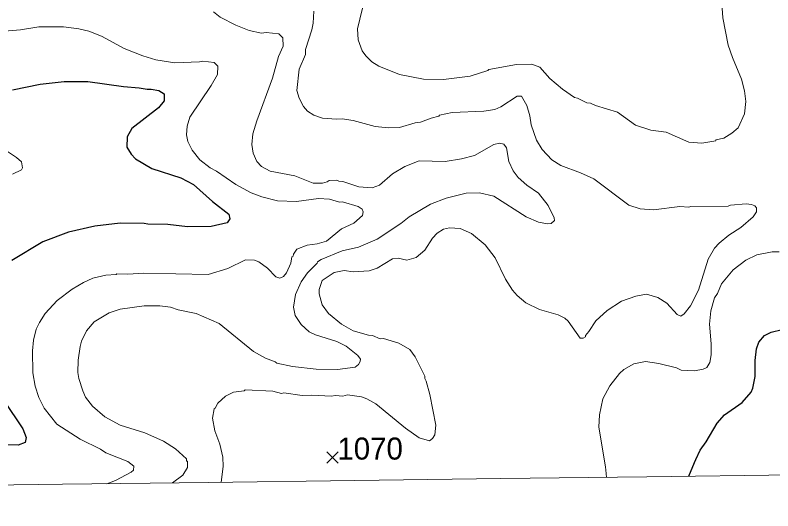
# Model space of a CAD drawing. Extents: x 265.7 to 292.1, y 7676.2 to 7704.2.
# Drawn here: x 287.156 to 289.907, y 7676.365 to 7678.165 of the extents above; entities that cross this region are included whole.
import ezdxf
from ezdxf.enums import TextEntityAlignment as Align

# ---------------------------------------------------------------- set-up
doc = ezdxf.new("R2010")
doc.units = 0
doc.header["$LTSCALE"] = 0.032
for name, color, linetype, lineweight in [('1', 7, 'Continuous', 25), ('2', 7, 'Continuous', 13), ('21', 7, 'Continuous', 25), ('63', 7, 'Continuous', 25)]:
    doc.layers.add(name, color=color, linetype=linetype, lineweight=lineweight)
doc.layers.add('61', color=7, linetype='Continuous')

msp = doc.modelspace()

# ---------------------------------------------------------------- linework, layer by layer
at = {"layer": '1'}
for points in [[(287.1465, 7677.8935), (287.2471, 7677.9142), (287.3333, 7677.9246), (287.4194, 7677.9238), (287.5487, 7677.9055), (287.6062, 7677.9015), (287.6349, 7677.8959), (287.6493, 7677.8967), (287.678, 7677.8911), (287.6971, 7677.8791), (287.6963, 7677.8536), (287.6764, 7677.8281), (287.579, 7677.7538), (287.5631, 7677.7227), (287.5615, 7677.686), (287.5766, 7677.6605), (287.5926, 7677.6429), (287.6516, 7677.6078), (287.7578, 7677.5743), (287.8033, 7677.5496), (287.8727, 7677.4881), (287.9317, 7677.4426), (287.9349, 7677.4259), (287.9253, 7677.4107), (287.8679, 7677.398), (287.7817, 7677.3964), (287.7099, 7677.4043), (287.6381, 7677.4059), (287.6237, 7677.4091), (287.5375, 7677.4099), (287.445, 7677.3987), (287.3492, 7677.3772), (287.2567, 7677.3421), (287.1433, 7677.2743)], [(289.6017, 7676.4904), (289.6218, 7676.5401), (289.6273, 7676.5511), (289.6425, 7676.5848), (289.6649, 7676.616), (289.704, 7676.6838), (289.7311, 7676.7141), (289.795, 7676.7588), (289.8277, 7676.7955), (289.8341, 7676.8099), (289.8428, 7676.853), (289.8428, 7676.9104), (289.8468, 7676.9535), (289.8556, 7676.9774), (289.8764, 7677.0014), (289.9003, 7677.0133), (289.941, 7677.0237)], [(287.1146, 7676.7652), (287.184, 7676.663), (287.196, 7676.6311), (287.1928, 7676.6128), (287.1673, 7676.604), (287.1242, 7676.6048)]]:
    msp.add_lwpolyline(points, dxfattribs=at)
at = {"layer": '2'}
msp.add_line((287.4887, 7676.4636), (287.52, 7676.4752), dxfattribs=at)
for points in [[(289.7208, 7678.227), (289.7255, 7678.1552), (289.7447, 7678.0563), (289.7599, 7678.0108), (289.7926, 7677.9326), (289.8037, 7677.8903), (289.8085, 7677.852), (289.8037, 7677.8073), (289.7806, 7677.7555), (289.7575, 7677.7363), (289.7287, 7677.7187), (289.7, 7677.7124), (289.6992, 7677.7092), (289.6489, 7677.7004), (289.6011, 7677.7044), (289.5197, 7677.7403), (289.4638, 7677.7475), (289.408, 7677.7658), (289.3425, 7677.8129), (289.2627, 7677.8368), (289.2444, 7677.8456), (289.2308, 7677.8472), (289.1973, 7677.864), (289.1869, 7677.8656), (289.143, 7677.8967), (289.0976, 7677.935), (289.0608, 7677.9757), (289.0313, 7677.9869), (288.9755, 7677.9861), (288.8757, 7677.9677), (288.8717, 7677.9637), (288.8079, 7677.9438), (288.7105, 7677.9318), (288.6387, 7677.9326), (288.551, 7677.9493), (288.4759, 7677.9797), (288.4512, 7677.9956), (288.4289, 7678.0172), (288.4153, 7678.0355), (288.4009, 7678.0754), (288.3993, 7678.1153), (288.4249, 7678.227)], [(287.8759, 7678.1768), (287.8998, 7678.1584), (287.9573, 7678.1289), (288.0051, 7678.1097), (288.0498, 7678.1002), (288.0674, 7678.1026), (288.1129, 7678.0978), (288.128, 7678.0826), (288.1288, 7678.0523), (288.1121, 7678.0148), (288.0897, 7677.9366), (288.0331, 7677.7818), (288.0187, 7677.7339), (288.0155, 7677.6956), (288.0203, 7677.6637), (288.0339, 7677.6334), (288.0498, 7677.6158), (288.0817, 7677.599), (288.1711, 7677.5815), (288.2381, 7677.5544), (288.2717, 7677.5552), (288.2892, 7677.5599), (288.2956, 7677.5647), (288.3227, 7677.5663), (288.3315, 7677.5623), (288.3459, 7677.5615), (288.4041, 7677.5416), (288.452, 7677.5384), (288.4783, 7677.548), (288.5254, 7677.5887), (288.5701, 7677.6158), (288.6228, 7677.6358), (288.7169, 7677.6342), (288.776, 7677.6437), (288.8239, 7677.6557), (288.8941, 7677.6956), (288.914, 7677.7004), (288.93, 7677.6972), (288.9396, 7677.6836)], [(289.8412, 7677.473), (289.8293, 7677.4778), (289.8101, 7677.4801), (289.7527, 7677.4746), (289.7447, 7677.4714), (289.609, 7677.4706), (289.6011, 7677.4682), (289.5691, 7677.4706), (289.4734, 7677.4578), (289.4255, 7677.4618), (289.384, 7677.4754), (289.2563, 7677.5711), (289.2085, 7677.5927), (289.1367, 7677.619), (289.1039, 7677.6397), (289.0696, 7677.6773), (289.0489, 7677.7116), (289.0289, 7677.7674), (289.0241, 7677.7993), (289.0138, 7677.8376), (288.9938, 7677.8704), (288.9787, 7677.8711), (288.9188, 7677.8321), (288.8973, 7677.8225), (288.8574, 7677.8161), (288.7425, 7677.8113), (288.6962, 7677.8017), (288.6946, 7677.7985), (288.6659, 7677.7914), (288.6276, 7677.7762), (288.6084, 7677.7738), (288.551, 7677.757), (288.5111, 7677.7562), (288.4632, 7677.7602), (288.3834, 7677.7826), (288.3435, 7677.789), (288.3227, 7677.7874), (288.2717, 7677.7906), (288.2397, 7677.8025), (288.2174, 7677.8169), (288.203, 7677.8329), (288.1871, 7677.8632), (288.1791, 7677.8919), (288.1871, 7677.9685), (288.2094, 7678.0228), (288.2102, 7678.0403), (288.2326, 7678.1121), (288.2373, 7678.1361), (288.2397, 7678.18)], [(287.52, 7676.4752), (287.5774, 7676.505), (287.5854, 7676.5122), (287.587, 7676.5274), (287.5647, 7676.5441), (287.4849, 7676.5761), (287.4657, 7676.5888), (287.3923, 7676.6255), (287.3069, 7676.6798), (287.2614, 7676.7373), (287.2415, 7676.7764), (287.2287, 7676.8178), (287.2199, 7676.8657), (287.2191, 7676.9455), (287.2223, 7676.9854), (287.2327, 7677.0253), (287.2439, 7677.0493), (287.2654, 7677.0812), (287.3085, 7677.1283), (287.3628, 7677.1697), (287.4035, 7677.1945), (287.4378, 7677.2096), (287.4849, 7677.2208), (287.5232, 7677.2232), (287.5248, 7677.2256), (287.5647, 7677.224), (287.6221, 7677.228), (287.8567, 7677.2232), (287.9285, 7677.2455), (287.9924, 7677.2767), (288.0243, 7677.2759), (288.0403, 7677.2695), (288.0722, 7677.2463), (288.1017, 7677.2152), (288.1169, 7677.2104), (288.1304, 7677.216), (288.1416, 7677.2288), (288.1567, 7677.2647), (288.1599, 7677.287), (288.1647, 7677.2902), (288.1663, 7677.2974), (288.1791, 7677.315), (288.2166, 7677.3293), (288.2525, 7677.3341), (288.2868, 7677.3445), (288.3411, 7677.3892), (288.385, 7677.4099), (288.4169, 7677.4379), (288.4193, 7677.4514), (288.4153, 7677.4602), (288.4009, 7677.4698), (288.3443, 7677.4873), (288.3339, 7677.4865), (288.2972, 7677.4969), (288.2573, 7677.4993), (288.1775, 7677.4881), (288.1089, 7677.4913), (288.0514, 7677.5049), (288.0131, 7677.52), (287.9565, 7677.5504), (287.887, 7677.599), (287.8639, 7677.611), (287.8264, 7677.6397), (287.7985, 7677.6749), (287.7825, 7677.7068), (287.7777, 7677.7307), (287.7809, 7677.7626), (287.7897, 7677.7946), (287.8679, 7677.9095), (287.8902, 7677.9502), (287.8918, 7677.9805), (287.8786, 7677.993), (287.8374, 7677.9986), (287.8248, 7677.9956), (287.7354, 7677.9924), (287.6668, 7678.0028), (287.6189, 7678.0172), (287.5519, 7678.0435), (287.4697, 7678.089), (287.4234, 7678.1073), (287.3875, 7678.1161), (287.3317, 7678.1225), (287.2423, 7678.1225), (287.1753, 7678.1113), (287.0875, 7678.105)], [(287.113, 7677.6796), (287.1609, 7677.6485), (287.1784, 7677.6326), (287.1824, 7677.6102), (287.1792, 7677.6038), (287.1465, 7677.5871)], [(288.9396, 7677.6836), (288.9483, 7677.6334), (288.9635, 7677.5999), (288.9826, 7677.5759), (289.013, 7677.548), (289.0553, 7677.5184), (289.0904, 7677.4738)], [(289.0904, 7677.4738), (289.1127, 7677.4291), (289.1135, 7677.4195), (289.1015, 7677.4083), (289.0888, 7677.4067), (289.0553, 7677.4139), (289.0106, 7677.4323), (288.8933, 7677.5081), (288.8414, 7677.5193), (288.7935, 7677.5185), (288.7201, 7677.5009), (288.6643, 7677.4786), (288.5861, 7677.4323), (288.5557, 7677.4083), (288.4696, 7677.3517), (288.4025, 7677.3222), (288.3435, 7677.3094), (288.2669, 7677.2783), (288.2533, 7677.2687), (288.2525, 7677.2647), (288.2174, 7677.2296), (288.1943, 7677.1961), (288.1735, 7677.1506), (288.1663, 7677.1051), (288.1719, 7677.0748), (288.1943, 7677.0421), (288.2238, 7677.0149), (288.2461, 7677.0038), (288.3243, 7676.9798), (288.3578, 7676.9631), (288.4001, 7676.9288), (288.4097, 7676.916), (288.4089, 7676.9072), (288.4025, 7676.896), (288.3906, 7676.8873), (288.3259, 7676.8785), (288.2493, 7676.8793), (288.1631, 7676.8889), (288.1057, 7676.9016), (288.1001, 7676.9064), (288.065, 7676.9192), (288.0211, 7676.9439), (287.8966, 7677.0453), (287.8136, 7677.0812), (287.7482, 7677.0947), (287.7195, 7677.1043), (287.6812, 7677.1091), (287.6237, 7677.1099), (287.5375, 7677.0979), (287.4976, 7677.0836), (287.4426, 7677.0508), (287.4154, 7677.0189), (287.3971, 7676.9806), (287.3915, 7676.9615), (287.3843, 7676.912), (287.3835, 7676.8673), (287.3867, 7676.845), (287.4011, 7676.8003), (287.4115, 7676.778), (287.4362, 7676.7452), (287.4817, 7676.7061), (287.5375, 7676.6766), (287.6269, 7676.6479), (287.6939, 7676.6176), (287.7386, 7676.5904), (287.7777, 7676.5537), (287.7785, 7676.5457), (287.7817, 7676.5457), (287.7817, 7676.5226), (287.7649, 7676.4939), (287.7268, 7676.4668)], [(289.7112, 7677.3365), (289.7463, 7677.366), (289.7902, 7677.394), (289.8357, 7677.4331), (289.8468, 7677.4514), (289.8468, 7677.4658), (289.8412, 7677.473)], [(287.9033, 7676.469), (287.911, 7676.5258), (287.9102, 7676.5593), (287.899, 7676.6072), (287.8807, 7676.6551), (287.8719, 7676.7021), (287.8783, 7676.7349), (287.8823, 7676.7373), (287.8918, 7676.7556), (287.919, 7676.7819), (287.9485, 7676.7963), (287.9876, 7676.8011), (287.9908, 7676.8043), (288.0913, 7676.7995), (288.1232, 7676.7915), (288.1312, 7676.7931), (288.1983, 7676.7835), (288.2334, 7676.7851), (288.3036, 7676.7811), (288.3195, 7676.7843), (288.3451, 7676.7811), (288.3626, 7676.7859), (288.4137, 7676.7787), (288.4329, 7676.7716), (288.4656, 7676.7532), (288.5725, 7676.6654), (288.6228, 7676.6295), (288.6603, 7676.6192), (288.6706, 7676.6271), (288.6794, 7676.6407), (288.6826, 7676.6758), (288.6619, 7676.7875), (288.6483, 7676.8354), (288.6427, 7676.845), (288.6427, 7676.8546), (288.6084, 7676.9248), (288.5884, 7676.9511), (288.5494, 7676.9734), (288.4935, 7676.991), (288.4807, 7676.9902), (288.4528, 7677.0022), (288.4392, 7677.003), (288.3834, 7677.0189), (288.3411, 7677.0429), (288.2932, 7677.0812), (288.2709, 7677.1131), (288.2597, 7677.153), (288.2597, 7677.169), (288.2701, 7677.2009), (288.314, 7677.2304), (288.3499, 7677.2376), (288.3834, 7677.2328), (288.4408, 7677.2368), (288.4696, 7677.2463), (288.5262, 7677.2799), (288.5462, 7677.2823), (288.5781, 7677.2759), (288.6116, 7677.2854), (288.6435, 7677.3118), (288.6714, 7677.3557), (288.6874, 7677.3732), (288.7105, 7677.3884), (288.7329, 7677.3924), (288.7712, 7677.39), (288.8127, 7677.3724), (288.8621, 7677.3309), (288.8989, 7677.2839), (288.9356, 7677.2065), (288.9619, 7677.1658), (288.9787, 7677.1466), (289.0098, 7677.1203), (289.06, 7677.0963), (289.1271, 7677.0764), (289.1518, 7677.0644), (289.1638, 7677.0532), (289.2077, 7676.9918), (289.218, 7676.9926), (289.226, 7676.9974), (289.226, 7677.0014), (289.2388, 7677.0157), (289.2643, 7677.0556), (289.305, 7677.0931), (289.3569, 7677.1259), (289.4096, 7677.1442), (289.4479, 7677.1514), (289.4894, 7677.1402), (289.5213, 7677.1187), (289.5596, 7677.078), (289.5731, 7677.0724), (289.5843, 7677.0804), (289.6074, 7677.1099), (289.6362, 7677.1658), (289.6721, 7677.2791), (289.6952, 7677.319), (289.7112, 7677.3365)], [(289.9298, 7677.3054), (289.9043, 7677.3054), (289.8484, 7677.2942), (289.8085, 7677.2759), (289.7623, 7677.24), (289.7208, 7677.1889), (289.7056, 7677.1546), (289.6952, 7677.1386), (289.6817, 7677.0908), (289.6769, 7677.0429), (289.6833, 7676.9711), (289.6833, 7676.9312), (289.6777, 7676.904), (289.6665, 7676.8857), (289.6537, 7676.8793), (289.6218, 7676.8737), (289.5739, 7676.8761), (289.5564, 7676.8841), (289.4925, 7676.9), (289.4447, 7676.9072), (289.4016, 7676.8992), (289.3657, 7676.8785), (289.3497, 7676.8633), (289.3154, 7676.8186), (289.2899, 7676.7716), (289.2771, 7676.7141), (289.2755, 7676.6686), (289.2986, 7676.5242), (289.3018, 7676.5009), (289.3033, 7676.4863)]]:
    msp.add_lwpolyline(points, dxfattribs=at)
at = {"layer": '21'}
for p, q in [((288.2879, 7676.5789), (288.3291, 7676.5377)), ((288.3291, 7676.5789), (288.2879, 7676.5377))]:
    msp.add_line(p, q, dxfattribs=at)
at = {"layer": '63', "lineweight": 13}
msp.add_lwpolyline([(292.1022, 7676.5221), (291.5717, 7676.5154), (291.0411, 7676.5087), (290.5106, 7676.5021), (289.9801, 7676.4954), (289.4496, 7676.4887), (288.9191, 7676.4819), (288.3886, 7676.4752), (287.858, 7676.4684), (287.3275, 7676.4616), (286.797, 7676.4548), (286.2665, 7676.448), (285.7359, 7676.4412), (285.2054, 7676.4343), (284.6749, 7676.4275), (284.1443, 7676.4206), (283.6138, 7676.4137), (283.0833, 7676.4067), (282.5527, 7676.3998), (282.0222, 7676.3929), (281.4917, 7676.3859), (280.9611, 7676.3789), (280.4306, 7676.3719), (279.9, 7676.3649)], dxfattribs=at)

# ---------------------------------------------------------------- texts
at = {"layer": '61'}
msp.add_text('1070', height=0.08, dxfattribs=at).set_placement((288.4446, 7676.5511), align=Align.CENTER)

doc.saveas('drawing.dxf')
